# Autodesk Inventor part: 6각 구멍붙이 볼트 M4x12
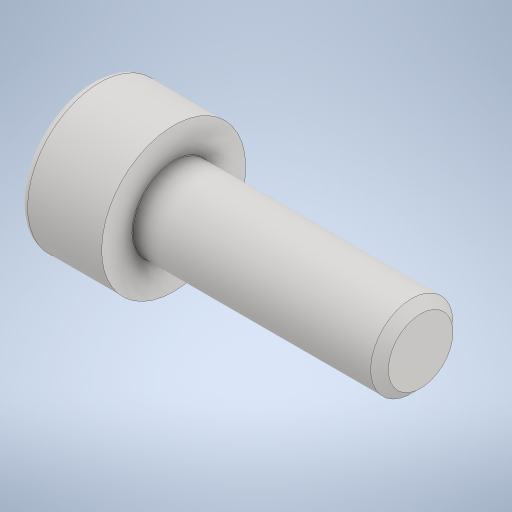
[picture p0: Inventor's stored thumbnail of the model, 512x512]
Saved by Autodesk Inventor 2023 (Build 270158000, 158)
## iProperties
Created: 2026-08
Part Number: 6각 구멍붙이 볼트 M4x12
Material: 스테인리스강
Description: 6각 소켓 머리 캡 나사
Document SubType Name: Modeling
Designer: home
Density: 8.08 g/cm^3
Appearance: 기본값
Author: jhkim
Sending System: Autodesk Inventor 2027
Preprocessor: ST-DEVELOPER v20.1
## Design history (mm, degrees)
feature "Solid1"
node "솔리드1"
